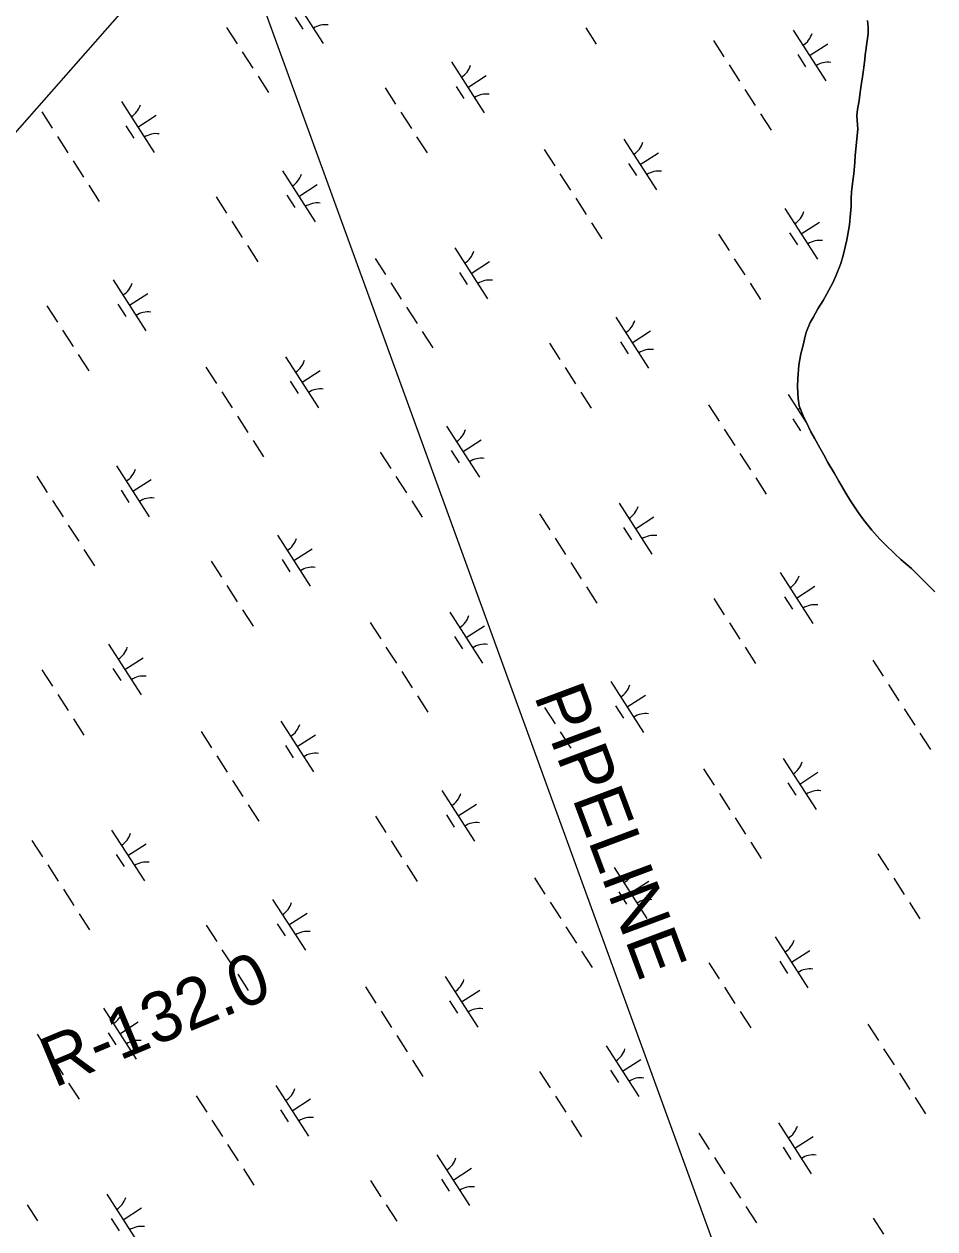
# Model space of a CAD drawing. Extents: x 3937982 to 3958556, y 219448 to 241894.
# Drawn here: x 3950623 to 3951376, y 227398 to 228394 of the extents above; entities that cross this region are included whole.
import ezdxf

# ---------------------------------------------------------------- set-up
doc = ezdxf.new("R2010")
doc.units = 0
for name, color, linetype in [('V-GRID-MAJR', 7, 'Continuous'), ('V-RIVR-RANG-IDEN', 7, 'Continuous'), ('V-TOPO-SHOR', 7, 'Continuous'), ('V-UTIL-IDEN', 7, 'Continuous'), ('V-UTIL-LINE', 7, 'Continuous'), ('V-WETL-SWMP', 7, 'Continuous')]:
    doc.layers.add(name, color=color, linetype=linetype)

msp = doc.modelspace()

# ---------------------------------------------------------------- linework, layer by layer
at = {"layer": 'V-GRID-MAJR'}
msp.add_spline([(3951546.997, 222374.883), (3951510.765, 224351.731), (3951399.696, 230411.652), (3951288.627, 236471.56), (3951286.871, 236567.353)], degree=3, dxfattribs=at)
at = {"layer": 'V-TOPO-SHOR'}
for points in [[(3951318.114, 228365.405), (3951318.487, 228368.905), (3951319.054, 228372.405), (3951319.619, 228376.683), (3951320.371, 228382.516), (3951320.936, 228386.405), (3951320.914, 228391.847), (3951320.502, 228397.286)], [(3951266.861, 228127.886), (3951269.15, 228137.419), (3951269.916, 228140.34), (3951272.994, 228147.543), (3951275.501, 228151.829), (3951279.36, 228158.842), (3951283.798, 228165.858), (3951286.884, 228171.314), (3951291.703, 228180.468), (3951294.593, 228186.698), (3951298.242, 228196.433), (3951300.157, 228203.048), (3951303.211, 228215.889), (3951303.975, 228219.002), (3951305.488, 228228.336), (3951306.422, 228237.669), (3951306.784, 228243.502), (3951306.95, 228249.914), (3951307.315, 228255.552), (3951308.247, 228264.885), (3951309, 228270.523), (3951309.93, 228279.858), (3951310.295, 228285.689), (3951312.339, 228307.465), (3951311.706, 228318.733), (3951312.269, 228323.79), (3951313.401, 228331.179), (3951314.159, 228335.846), (3951314.911, 228341.875), (3951315.478, 228345.375), (3951316.232, 228350.819), (3951316.799, 228354.516), (3951317.551, 228360.737), (3951318.114, 228365.405)], [(3951376.181, 227925.075), (3951370.52, 227930.686), (3951362.128, 227939.202), (3951356.663, 227944.23), (3951348.08, 227951.772), (3951342.616, 227956.802), (3951335.395, 227963.962), (3951330.711, 227968.607), (3951324.072, 227975.961), (3951317.428, 227984.291), (3951312.93, 227990.295), (3951306.281, 228000.179), (3951302.561, 228006.577), (3951296.688, 228016.463), (3951293.161, 228022.86), (3951287.681, 228031.97), (3951284.351, 228038.175), (3951281.021, 228043.992), (3951276.712, 228051.94), (3951273.578, 228057.175), (3951269.853, 228064.933), (3951267.301, 228070.556), (3951263.963, 228078.9), (3951262.965, 228084.726), (3951262.535, 228094.44), (3951262.894, 228101.438), (3951263.623, 228112.325), (3951265.333, 228121.662), (3951266.861, 228127.886)]]:
    msp.add_lwpolyline(points, dxfattribs=at)
at = {"layer": 'V-UTIL-LINE'}
msp.add_line((3950898.169, 228625.327), (3949080.141, 226562.604), dxfattribs=at)
msp.add_lwpolyline([(3950785.675, 228505.622), (3951648.465, 226135.699)], dxfattribs=at)
at = {"layer": 'V-WETL-SWMP'}
for p, q in [((3950843.315, 228420.288), (3950870.378, 228378.245)), ((3950790.44, 228391.512), (3950799.1, 228378.058)), ((3950847.111, 228400.136), (3950853.606, 228390.045)), ((3951087.426, 228391.26), (3951096.086, 228377.806)), ((3951193.013, 228380.734), (3951201.673, 228367.28)), ((3951258.878, 228389.329), (3951285.94, 228347.285)), ((3950803.43, 228371.332), (3950812.09, 228357.878)), ((3951272.409, 228368.307), (3951287.545, 228378.05)), ((3950976.445, 228362.989), (3951003.507, 228320.946)), ((3951206.003, 228360.553), (3951214.663, 228347.099)), ((3951262.674, 228369.176), (3951269.169, 228359.086)), ((3950816.42, 228351.151), (3950825.08, 228337.697)), ((3950989.976, 228341.968), (3951005.111, 228351.71)), ((3950921.579, 228341.592), (3950930.239, 228328.138)), ((3950980.241, 228342.837), (3950986.736, 228332.747)), ((3951218.993, 228340.372), (3951227.653, 228326.918)), ((3950637.583, 228321.664), (3950646.243, 228308.21)), ((3950703.448, 228330.258), (3950730.51, 228288.215)), ((3950934.569, 228321.412), (3950943.228, 228307.958)), ((3950716.979, 228309.237), (3950732.115, 228318.979)), ((3951231.983, 228320.192), (3951240.642, 228306.738)), ((3950650.573, 228301.483), (3950659.233, 228288.029)), ((3950707.244, 228310.106), (3950713.739, 228300.016)), ((3950947.558, 228301.231), (3950956.218, 228287.777)), ((3951053.146, 228290.704), (3951061.805, 228277.25)), ((3951119.011, 228299.299), (3951146.073, 228257.256)), ((3950663.563, 228281.302), (3950672.223, 228267.848)), ((3951132.542, 228278.278), (3951147.677, 228288.02)), ((3950836.577, 228272.96), (3950863.64, 228230.917)), ((3951122.807, 228279.147), (3951129.301, 228269.056)), ((3950676.553, 228261.121), (3950685.213, 228247.667)), ((3950850.109, 228251.938), (3950865.244, 228261.681)), ((3951066.135, 228270.524), (3951074.795, 228257.07)), ((3950781.711, 228251.563), (3950790.371, 228238.109)), ((3950840.373, 228252.807), (3950846.868, 228242.717)), ((3951079.125, 228250.343), (3951087.785, 228236.889)), ((3951252.14, 228242.001), (3951279.202, 228199.957)), ((3950794.701, 228231.382), (3950803.361, 228217.928)), ((3951092.115, 228230.162), (3951100.775, 228216.708)), ((3951255.936, 228221.848), (3951262.431, 228211.758)), ((3951265.671, 228220.979), (3951280.806, 228230.721)), ((3950807.691, 228211.201), (3950816.351, 228197.747)), ((3951197.274, 228220.604), (3951205.934, 228207.15)), ((3950979.143, 228209.27), (3951006.206, 228167.226)), ((3950913.278, 228200.675), (3950921.938, 228187.221)), ((3950992.674, 228188.248), (3951007.81, 228197.991)), ((3951210.264, 228200.423), (3951218.924, 228186.969)), ((3950696.71, 228182.93), (3950723.772, 228140.887)), ((3950982.939, 228189.117), (3950989.434, 228179.027)), ((3950710.241, 228161.909), (3950725.377, 228171.651)), ((3950926.268, 228180.494), (3950934.928, 228167.04)), ((3951223.254, 228180.242), (3951231.913, 228166.788)), ((3950641.844, 228161.533), (3950650.504, 228148.079)), ((3950700.506, 228162.778), (3950707.001, 228152.688)), ((3950939.258, 228160.313), (3950947.918, 228146.859)), ((3951112.273, 228151.971), (3951139.335, 228109.928)), ((3950654.834, 228141.353), (3950663.494, 228127.899)), ((3950952.248, 228140.133), (3950960.908, 228126.679)), ((3951116.069, 228131.819), (3951122.563, 228121.728)), ((3951125.804, 228130.949), (3951140.939, 228140.692)), ((3951057.406, 228130.574), (3951066.066, 228117.12)), ((3950667.824, 228121.172), (3950676.484, 228107.718)), ((3950839.276, 228119.24), (3950866.338, 228077.197)), ((3950773.411, 228110.645), (3950782.071, 228097.191)), ((3950852.807, 228098.219), (3950867.943, 228107.961)), ((3951070.396, 228110.393), (3951079.056, 228096.939)), ((3950843.072, 228099.088), (3950849.567, 228088.997)), ((3950786.401, 228090.465), (3950795.061, 228077.011)), ((3951083.386, 228090.213), (3951092.046, 228076.759)), ((3951254.838, 228088.281), (3951269.818, 228065.009)), ((3951188.973, 228079.686), (3951197.633, 228066.232)), ((3950799.391, 228070.284), (3950808.051, 228056.83)), ((3950972.405, 228061.942), (3950999.468, 228019.898)), ((3951258.634, 228068.129), (3951265.129, 228058.038)), ((3951268.37, 228067.259), (3951268.701, 228067.473)), ((3951201.963, 228059.505), (3951210.623, 228046.051)), ((3950812.381, 228050.103), (3950821.041, 228036.649)), ((3950976.201, 228041.789), (3950982.696, 228031.699)), ((3950985.936, 228040.92), (3951001.072, 228050.662)), ((3950917.539, 228040.545), (3950926.199, 228027.091)), ((3951214.953, 228039.325), (3951223.613, 228025.871)), ((3950699.409, 228029.211), (3950726.471, 227987.167)), ((3950633.544, 228020.616), (3950642.204, 228007.162)), ((3950712.94, 228008.189), (3950728.075, 228017.931)), ((3950930.529, 228020.364), (3950939.189, 228006.91)), ((3951227.943, 228019.144), (3951236.603, 228005.69)), ((3950703.205, 228009.058), (3950709.7, 227998.968)), ((3950646.534, 228000.435), (3950655.194, 227986.981)), ((3950943.519, 228000.183), (3950952.179, 227986.729)), ((3951114.971, 227998.251), (3951142.033, 227956.208)), ((3951049.106, 227989.656), (3951057.766, 227976.203)), ((3951128.502, 227977.23), (3951143.638, 227986.972)), ((3950659.524, 227980.254), (3950668.183, 227966.8)), ((3951118.767, 227978.099), (3951125.262, 227968.009)), ((3950832.538, 227971.912), (3950859.6, 227929.869)), ((3951062.096, 227969.476), (3951070.756, 227956.022)), ((3950672.513, 227960.074), (3950681.173, 227946.62)), ((3950846.069, 227950.89), (3950861.205, 227960.633)), ((3950777.672, 227950.515), (3950786.332, 227937.061)), ((3950836.334, 227951.76), (3950842.829, 227941.669)), ((3951075.086, 227949.295), (3951083.746, 227935.841)), ((3951248.1, 227940.953), (3951275.163, 227898.91)), ((3950790.662, 227930.334), (3950799.322, 227916.88)), ((3951088.076, 227929.114), (3951096.736, 227915.66)), ((3951261.632, 227919.931), (3951276.767, 227929.674)), ((3951193.234, 227919.556), (3951201.894, 227906.102)), ((3951251.896, 227920.8), (3951258.391, 227910.71)), ((3950803.652, 227910.154), (3950812.312, 227896.7)), ((3950975.104, 227908.222), (3951002.166, 227866.179)), ((3950909.239, 227899.627), (3950917.899, 227886.173)), ((3950988.635, 227887.2), (3951003.771, 227896.943)), ((3951206.224, 227899.375), (3951214.884, 227885.921)), ((3950978.9, 227888.07), (3950985.395, 227877.979)), ((3950692.671, 227881.883), (3950719.733, 227839.839)), ((3950922.229, 227879.446), (3950930.889, 227865.992)), ((3951219.214, 227879.194), (3951227.874, 227865.74)), ((3950706.202, 227860.861), (3950721.337, 227870.603)), ((3951324.801, 227868.668), (3951333.461, 227855.214)), ((3950637.805, 227860.486), (3950646.465, 227847.032)), ((3950696.467, 227861.73), (3950702.962, 227851.64)), ((3950935.219, 227859.265), (3950943.879, 227845.812)), ((3951108.233, 227850.923), (3951135.295, 227808.88)), ((3951337.791, 227848.487), (3951346.451, 227835.033)), ((3950650.795, 227840.305), (3950659.454, 227826.851)), ((3950948.209, 227839.085), (3950956.869, 227825.631)), ((3951121.764, 227829.902), (3951136.9, 227839.644)), ((3951053.367, 227829.526), (3951062.027, 227816.072)), ((3951112.029, 227830.771), (3951118.524, 227820.681)), ((3951350.781, 227828.306), (3951359.441, 227814.852)), ((3950663.784, 227820.124), (3950672.444, 227806.67)), ((3950835.237, 227818.192), (3950862.299, 227776.149)), ((3950769.372, 227809.597), (3950778.032, 227796.144)), ((3950848.768, 227797.171), (3950863.903, 227806.913)), ((3951066.357, 227809.346), (3951075.017, 227795.892)), ((3951363.771, 227808.126), (3951372.431, 227794.672)), ((3950839.033, 227798.04), (3950845.528, 227787.95)), ((3950782.361, 227789.417), (3950791.021, 227775.963)), ((3951079.347, 227789.165), (3951088.007, 227775.711)), ((3951250.799, 227787.233), (3951277.861, 227745.19)), ((3951184.934, 227778.638), (3951193.594, 227765.184)), ((3951264.33, 227766.212), (3951279.466, 227775.954)), ((3950795.351, 227769.236), (3950804.011, 227755.782)), ((3951254.595, 227767.081), (3951261.09, 227756.99)), ((3950968.366, 227760.894), (3950995.428, 227718.851)), ((3951197.924, 227758.457), (3951206.584, 227745.004)), ((3950808.341, 227749.055), (3950817.001, 227735.601)), ((3950981.897, 227739.872), (3950997.033, 227749.615)), ((3950913.5, 227739.497), (3950922.16, 227726.043)), ((3950972.162, 227740.741), (3950978.657, 227730.651)), ((3951210.914, 227738.277), (3951219.574, 227724.823)), ((3950695.369, 227728.163), (3950722.432, 227686.12)), ((3950629.504, 227719.568), (3950638.164, 227706.114)), ((3950708.9, 227707.141), (3950724.036, 227716.884)), ((3950926.49, 227719.316), (3950935.15, 227705.862)), ((3951223.904, 227718.096), (3951232.564, 227704.642)), ((3950699.165, 227708.01), (3950705.66, 227697.92)), ((3951329.062, 227708.538), (3951337.722, 227695.084)), ((3950642.494, 227699.387), (3950651.154, 227685.933)), ((3950939.48, 227699.135), (3950948.14, 227685.681)), ((3951110.932, 227697.204), (3951137.994, 227655.16)), ((3951045.067, 227688.609), (3951053.727, 227675.155)), ((3951124.463, 227676.182), (3951139.598, 227685.924)), ((3951342.052, 227688.357), (3951350.712, 227674.903)), ((3950655.484, 227679.206), (3950664.144, 227665.753)), ((3951114.728, 227677.051), (3951121.223, 227666.961)), ((3950828.499, 227670.864), (3950855.561, 227628.821)), ((3951058.057, 227668.428), (3951066.717, 227654.974)), ((3951355.042, 227668.176), (3951363.702, 227654.722)), ((3950668.474, 227659.026), (3950677.134, 227645.572)), ((3950842.03, 227649.843), (3950857.165, 227659.585)), ((3950773.633, 227649.467), (3950782.292, 227636.013)), ((3950832.295, 227650.712), (3950838.79, 227640.622)), ((3951071.047, 227648.247), (3951079.706, 227634.793)), ((3951244.061, 227639.905), (3951271.123, 227597.862)), ((3950786.622, 227629.287), (3950795.282, 227615.833)), ((3951084.036, 227628.066), (3951092.696, 227614.613)), ((3951257.592, 227618.883), (3951272.728, 227628.626)), ((3951189.195, 227618.508), (3951197.855, 227605.054)), ((3951247.857, 227619.753), (3951254.352, 227609.662)), ((3950799.612, 227609.106), (3950808.272, 227595.652)), ((3950971.064, 227607.174), (3950998.127, 227565.131)), ((3950905.199, 227598.579), (3950913.859, 227585.125)), ((3950984.596, 227586.153), (3950999.731, 227595.895)), ((3951202.185, 227598.327), (3951210.845, 227584.873)), ((3950974.86, 227587.022), (3950981.355, 227576.931)), ((3950688.631, 227580.835), (3950715.694, 227538.792)), ((3950918.189, 227578.398), (3950926.849, 227564.945)), ((3951215.175, 227578.147), (3951223.835, 227564.693)), ((3950702.162, 227559.813), (3950717.298, 227569.556)), ((3951320.762, 227567.62), (3951329.422, 227554.166)), ((3950633.765, 227559.438), (3950642.425, 227545.984)), ((3950692.427, 227560.682), (3950698.922, 227550.592)), ((3950931.179, 227558.218), (3950939.839, 227544.764)), ((3951104.194, 227549.876), (3951131.256, 227507.832)), ((3951333.752, 227547.439), (3951342.412, 227533.985)), ((3950646.755, 227539.257), (3950655.415, 227525.803)), ((3950944.169, 227538.037), (3950952.829, 227524.583)), ((3951117.725, 227528.854), (3951132.86, 227538.596)), ((3951049.328, 227528.478), (3951057.988, 227515.025)), ((3951107.99, 227529.723), (3951114.485, 227519.633)), ((3951346.742, 227527.258), (3951355.402, 227513.805)), ((3950659.745, 227519.076), (3950668.405, 227505.622)), ((3950831.197, 227517.145), (3950858.259, 227475.101)), ((3950765.332, 227508.55), (3950773.992, 227495.096)), ((3950844.728, 227496.123), (3950859.864, 227505.865)), ((3951062.318, 227508.298), (3951070.977, 227494.844)), ((3951359.732, 227507.078), (3951368.391, 227493.624)), ((3950834.993, 227496.992), (3950841.488, 227486.902)), ((3950778.322, 227488.369), (3950786.982, 227474.915)), ((3951075.307, 227488.117), (3951083.967, 227474.663)), ((3951246.76, 227486.185), (3951273.822, 227444.142)), ((3951180.895, 227477.59), (3951189.554, 227464.137)), ((3951260.291, 227465.164), (3951275.426, 227474.906)), ((3950791.312, 227468.188), (3950799.972, 227454.734)), ((3951250.556, 227466.033), (3951257.05, 227455.943)), ((3950964.326, 227459.846), (3950991.389, 227417.803)), ((3951193.884, 227457.41), (3951202.544, 227443.956)), ((3950804.302, 227448.007), (3950812.962, 227434.554)), ((3950977.858, 227438.824), (3950992.993, 227448.567)), ((3950909.46, 227438.449), (3950918.12, 227424.995)), ((3950968.122, 227439.694), (3950974.617, 227429.603)), ((3951206.874, 227437.229), (3951215.534, 227423.775)), ((3950691.33, 227427.115), (3950718.392, 227385.072)), ((3950625.465, 227418.52), (3950634.125, 227405.066)), ((3950704.861, 227406.094), (3950719.997, 227415.836)), ((3950922.45, 227418.268), (3950931.11, 227404.814)), ((3951219.864, 227417.048), (3951228.524, 227403.594)), ((3950695.126, 227406.963), (3950701.621, 227396.872)), ((3951325.023, 227407.49), (3951333.683, 227394.036))]:
    msp.add_line(p, q, dxfattribs=at)
for points in [[(3951320.501, 228397.287), (3951320.913, 228391.847), (3951320.937, 228386.406), (3951320.371, 228382.516), (3951319.619, 228376.683), (3951319.054, 228372.405), (3951318.486, 228368.904), (3951318.113, 228365.404)], [(3951318.113, 228365.404), (3951317.55, 228360.738), (3951316.799, 228354.515), (3951316.232, 228350.82), (3951315.478, 228345.375), (3951314.91, 228341.875), (3951314.159, 228335.847), (3951313.402, 228331.179), (3951312.268, 228323.789), (3951311.706, 228318.734), (3951312.338, 228307.465), (3951310.295, 228285.689), (3951309.931, 228279.857), (3951309, 228270.524), (3951308.247, 228264.885), (3951307.315, 228255.553), (3951306.951, 228249.915), (3951306.784, 228243.501), (3951306.421, 228237.669), (3951305.489, 228228.336), (3951303.975, 228219.001), (3951303.211, 228215.888), (3951300.157, 228203.048), (3951298.242, 228196.432), (3951294.592, 228186.699), (3951291.703, 228180.468), (3951286.884, 228171.313), (3951283.798, 228165.858), (3951279.359, 228158.842), (3951275.502, 228151.829), (3951272.994, 228147.543), (3951269.916, 228140.339), (3951269.151, 228137.42), (3951266.86, 228127.887), (3951265.332, 228121.662), (3951263.623, 228112.326), (3951262.893, 228101.439), (3951262.535, 228094.441), (3951262.965, 228084.726), (3951263.962, 228078.9), (3951267.302, 228070.557), (3951269.853, 228064.932), (3951273.579, 228057.175), (3951276.711, 228051.941), (3951281.021, 228043.991), (3951284.35, 228038.175), (3951287.681, 228031.971), (3951293.162, 228022.86), (3951296.688, 228016.462), (3951302.561, 228006.576), (3951306.281, 228000.178), (3951312.931, 227990.296), (3951317.427, 227984.29), (3951324.071, 227975.962), (3951330.711, 227968.606), (3951335.395, 227963.962), (3951342.617, 227956.802), (3951348.08, 227951.773), (3951356.664, 227944.23), (3951362.127, 227939.201), (3951370.521, 227930.686), (3951376.181, 227925.075)]]:
    msp.add_lwpolyline(points, dxfattribs=at)
for centre, start, end in [((3950871.996, 228376.169), 81.996677, 123.540335), ((3951257.659, 228391.661), 301.99668, 343.540338), ((3950975.225, 228365.322), 301.99668, 343.540338), ((3951287.559, 228345.21), 81.996677, 123.540335), ((3951005.125, 228318.87), 81.996677, 123.540335), ((3950702.229, 228332.591), 301.99668, 343.540338), ((3950732.129, 228286.139), 81.996677, 123.540335), ((3951117.791, 228301.632), 301.99668, 343.540338), ((3951147.691, 228255.18), 81.996677, 123.540335), ((3950835.358, 228275.293), 301.99668, 343.540338), ((3950865.258, 228228.841), 81.996677, 123.540335), ((3951250.921, 228244.333), 301.99668, 343.540338), ((3951280.821, 228197.882), 81.996677, 123.540335), ((3950977.924, 228211.602), 301.99668, 343.540338), ((3951007.824, 228165.151), 81.996677, 123.540335), ((3950695.491, 228185.263), 301.99668, 343.540338), ((3950725.391, 228138.811), 81.996677, 123.540335), ((3951111.053, 228154.304), 301.99668, 343.540338), ((3951140.953, 228107.852), 81.996677, 123.540335), ((3950838.057, 228121.573), 301.99668, 343.540338), ((3950867.957, 228075.121), 81.996677, 123.540335), ((3951253.619, 228090.614), 301.99668, 309.144495), ((3950971.186, 228064.274), 301.99668, 343.540338), ((3951001.086, 228017.823), 81.996677, 123.540335), ((3950698.19, 228031.543), 301.99668, 343.540338), ((3950728.09, 227985.092), 81.996677, 123.540335), ((3951113.752, 228000.584), 301.99668, 343.540338), ((3950831.319, 227974.245), 301.99668, 343.540338), ((3951143.652, 227954.132), 81.996677, 123.540335), ((3950861.219, 227927.793), 81.996677, 123.540335), ((3951246.881, 227943.286), 301.99668, 343.540338), ((3951276.781, 227896.834), 81.996677, 123.540335), ((3950973.885, 227910.555), 301.99668, 343.540338), ((3950691.451, 227884.215), 301.99668, 343.540338), ((3951003.785, 227864.103), 81.996677, 123.540335), ((3950721.352, 227837.764), 81.996677, 123.540335), ((3951107.014, 227853.256), 301.99668, 343.540338), ((3951136.914, 227806.804), 81.996677, 123.540335), ((3950834.017, 227820.525), 301.99668, 343.540338), ((3950863.917, 227774.073), 81.996677, 123.540335), ((3951249.58, 227789.566), 301.99668, 343.540338), ((3950967.147, 227763.227), 301.99668, 343.540338), ((3951279.48, 227743.114), 81.996677, 123.540335), ((3950997.047, 227716.775), 81.996677, 123.540335), ((3950694.15, 227730.496), 301.99668, 343.540338), ((3950724.05, 227684.044), 81.996677, 123.540335), ((3951109.712, 227699.536), 301.99668, 343.540338), ((3950827.279, 227673.197), 301.99668, 343.540338), ((3951139.612, 227653.085), 81.996677, 123.540335), ((3950857.179, 227626.745), 81.996677, 123.540335), ((3951242.842, 227642.238), 301.99668, 343.540338), ((3950969.845, 227609.507), 301.99668, 343.540338), ((3951272.742, 227595.786), 81.996677, 123.540335), ((3950687.412, 227583.168), 301.99668, 343.540338), ((3950999.745, 227563.055), 81.996677, 123.540335), ((3950717.312, 227536.716), 81.996677, 123.540335), ((3951102.974, 227552.208), 301.99668, 343.540338), ((3950829.978, 227519.477), 301.99668, 343.540338), ((3951132.874, 227505.757), 81.996677, 123.540335), ((3950859.878, 227473.026), 81.996677, 123.540335), ((3951245.54, 227488.518), 301.99668, 343.540338), ((3950963.107, 227462.179), 301.99668, 343.540338), ((3951275.44, 227442.066), 81.996677, 123.540335), ((3950690.111, 227429.448), 301.99668, 343.540338), ((3950993.007, 227415.727), 81.996677, 123.540335), ((3950720.011, 227382.996), 81.996677, 123.540335)]:
    msp.add_arc(centre, 17.623, start, end, dxfattribs=at)

# ---------------------------------------------------------------- texts
at = {"layer": 'V-RIVR-RANG-IDEN'}
msp.add_text('R-132.0', height=41.5, rotation=22.623873, dxfattribs=at).set_placement((3950647.886, 227514.855))
at = {"layer": 'V-UTIL-IDEN'}
msp.add_text('PIPELINE', height=41.9999, rotation=290.47036, dxfattribs=at).set_placement((3951044.356, 227839.294))

doc.saveas('drawing.dxf')
